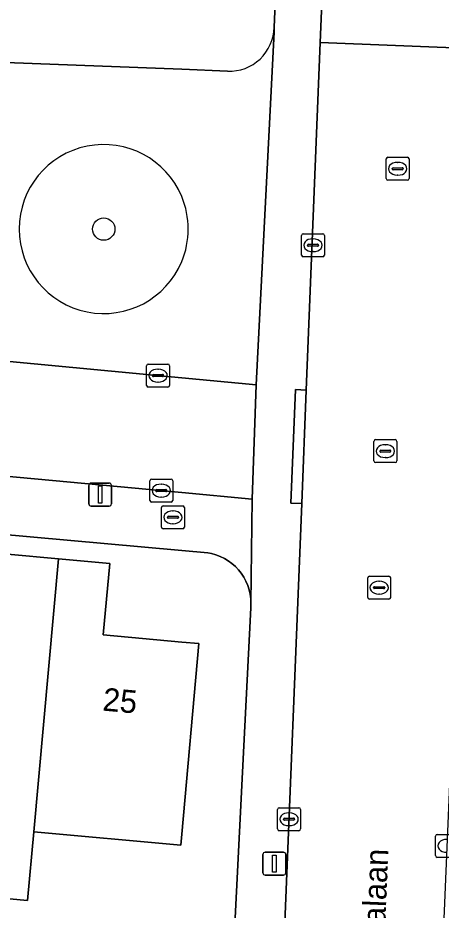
# Model space of a CAD drawing. Extents: x 161354 to 162026, y 386504 to 387460.
# Drawn here: x 161492.87 to 161511.3, y 386914.9 to 386953.74 of the extents above; entities that cross this region are included whole.
import ezdxf

# ---------------------------------------------------------------- set-up
doc = ezdxf.new("R2010")
doc.units = 0
for name, color, linetype in [('IMGEO_Boom', 7, 'Continuous'), ('IMGEO_Brandkraan', 7, 'Continuous'), ('IMGEO_Erf', 7, 'Continuous'), ('IMGEO_Kolk', 7, 'Continuous'), ('IMGEO_Lichtmast', 7, 'Continuous'), ('IMGEO_Muur', 7, 'Continuous'), ('IMGEO_Openbare_ruimte_label', 7, 'Continuous'), ('IMGEO_Pand', 7, 'Continuous'), ('IMGEO_Pand_nummerreeks', 7, 'Continuous'), ('IMGEO_Rijbaan_lokaal_open', 7, 'Continuous'), ('IMGEO_Rioolput', 7, 'Continuous'), ('IMGEO_Terreindeel_open', 7, 'Continuous'), ('IMGEO_Voetpad_open', 7, 'Continuous')]:
    doc.layers.add(name, color=color, linetype=linetype)

msp = doc.modelspace()

# ---------------------------------------------------------------- linework, layer by layer
at = {"layer": 'IMGEO_Boom'}
msp.add_circle((161496.605, 386944.55), 0.489, dxfattribs=at)
at = {"layer": 'IMGEO_Brandkraan'}
for p, q in [((161499.194, 386932.499), (161500.046, 386932.499)), ((161499.119, 386931.573), (161499.119, 386932.425)), ((161499.607, 386932.279), (161499.632, 386932.279)), ((161500.12, 386932.425), (161500.12, 386931.573)), ((161499.378, 386931.993), (161499.378, 386932.005)), ((161499.816, 386931.956), (161499.418, 386931.956)), ((161499.421, 386932.042), (161499.819, 386932.042)), ((161499.63, 386931.719), (161499.605, 386931.719)), ((161499.862, 386932.005), (161499.862, 386931.993)), ((161500.046, 386931.499), (161499.194, 386931.499))]:
    msp.add_line(p, q, dxfattribs=at)
for points in [[(161499.194, 386932.499), (161500.046, 386932.499)], [(161499.119, 386931.573), (161499.119, 386932.425)], [(161500.12, 386932.425), (161500.12, 386931.573)], [(161500.046, 386931.499), (161499.194, 386931.499)]]:
    msp.add_lwpolyline(points, dxfattribs=at)
for centre, radius, start, end in [((161499.196, 386932.423), 0.0765, 91.552, 178.448), ((161499.196, 386932.423), 0.0765, 91.552, 178.448), ((161500.044, 386932.423), 0.0765, 1.552, 88.448), ((161500.044, 386932.423), 0.0765, 1.552, 88.448), ((161499.418, 386932.002), 0.0403, 85.8775, 175.7526), ((161499.415, 386931.992), 0.0366, 178.938, 274.7102), ((161499.819, 386931.999), 0.043, 264.8664, 352.4533), ((161499.823, 386932.004), 0.0386, 1.7309, 96.639), ((161499.196, 386931.575), 0.0765, 181.552, 268.448), ((161499.196, 386931.575), 0.0765, 181.552, 268.448), ((161500.044, 386931.575), 0.0765, 271.552, 358.448), ((161500.044, 386931.575), 0.0765, 271.552, 358.448)]:
    msp.add_arc(centre, radius, start, end, dxfattribs=at)
for centre, major_axis, ratio, start_param, end_param in [((161499.606, 386931.999), (-0.387, 0.002), 0.722429, 4.712389, 7.853982), ((161499.631, 386931.999), (-0.39, 0.002), 0.717154, 1.570796, 4.712389)]:
    msp.add_ellipse(centre, major_axis=major_axis, ratio=ratio, start_param=start_param, end_param=end_param, dxfattribs=at)
at = {"layer": 'IMGEO_Erf'}
for points in [[(161504.021, 386953.33), (161504.232, 386958.325)], [(161429.855, 386954.16), (161500, 386951.511), (161502.002, 386951.426)], [(161502.252, 386913.113), (161502.647, 386920.904), (161503.008, 386928.059), (161503.017, 386928.258), (161503.009, 386928.456), (161502.982, 386928.653), (161502.938, 386928.847), (161502.878, 386929.036), (161502.8, 386929.219), (161502.706, 386929.395), (161502.597, 386929.561), (161502.474, 386929.717), (161502.337, 386929.861), (161502.188, 386929.992), (161502.028, 386930.11), (161501.858, 386930.213), (161501.679, 386930.3), (161501.493, 386930.371), (161501.302, 386930.425), (161501.138, 386930.457), (161500, 386930.56), (161439.113, 386936.044)], [(161492.422, 386930.389), (161494.642, 386930.187), (161496.866, 386929.985), (161496.584, 386926.877), (161500, 386926.567), (161500.753, 386926.499), (161500, 386918.206), (161499.956, 386917.721), (161493.563, 386918.301), (161493.292, 386915.317), (161487.143, 386915.876)]]:
    msp.add_lwpolyline(points, dxfattribs=at)
msp.add_arc((161502.081, 386953.365), 1.941, 267.6727, 358.9691, dxfattribs=at)
at = {"layer": 'IMGEO_Kolk'}
for p, q in [((161505.217, 386943.419), (161505.217, 386944.271)), ((161505.292, 386944.345), (161506.144, 386944.345)), ((161505.705, 386944.125), (161505.73, 386944.125)), ((161506.218, 386944.271), (161506.218, 386943.419)), ((161505.476, 386943.839), (161505.476, 386943.851)), ((161505.914, 386943.802), (161505.516, 386943.802)), ((161505.519, 386943.888), (161505.917, 386943.888)), ((161505.96, 386943.851), (161505.96, 386943.839)), ((161506.144, 386943.345), (161505.292, 386943.345)), ((161505.728, 386943.565), (161505.703, 386943.565)), ((161498.547, 386938.67), (161499.399, 386938.67)), ((161498.472, 386937.744), (161498.472, 386938.596)), ((161498.96, 386938.45), (161498.985, 386938.45)), ((161499.473, 386938.596), (161499.473, 386937.744)), ((161498.731, 386938.164), (161498.731, 386938.176)), ((161499.169, 386938.127), (161498.771, 386938.127)), ((161498.774, 386938.213), (161499.172, 386938.213)), ((161498.983, 386937.89), (161498.958, 386937.89)), ((161499.215, 386938.176), (161499.215, 386938.164)), ((161499.399, 386937.67), (161498.547, 386937.67)), ((161498.688, 386933.663), (161499.54, 386933.663)), ((161498.613, 386932.737), (161498.613, 386933.589)), ((161499.101, 386933.443), (161499.126, 386933.443)), ((161499.614, 386933.589), (161499.614, 386932.737)), ((161498.872, 386933.157), (161498.872, 386933.169)), ((161499.31, 386933.12), (161498.912, 386933.12)), ((161498.915, 386933.206), (161499.313, 386933.206)), ((161499.124, 386932.883), (161499.099, 386932.883)), ((161499.356, 386933.169), (161499.356, 386933.157)), ((161499.54, 386932.663), (161498.688, 386932.663)), ((161504.176, 386918.429), (161504.176, 386919.281)), ((161504.251, 386919.355), (161505.103, 386919.355)), ((161505.177, 386919.281), (161505.177, 386918.429)), ((161504.435, 386918.849), (161504.435, 386918.861)), ((161504.478, 386918.898), (161504.876, 386918.898)), ((161504.664, 386919.135), (161504.689, 386919.135)), ((161504.919, 386918.861), (161504.919, 386918.849)), ((161504.873, 386918.812), (161504.475, 386918.812)), ((161504.687, 386918.575), (161504.662, 386918.575)), ((161505.103, 386918.355), (161504.251, 386918.355)), ((161511.056, 386917.269), (161511.056, 386918.121)), ((161511.131, 386918.195), (161511.983, 386918.195)), ((161511.983, 386917.195), (161511.131, 386917.195))]:
    msp.add_line(p, q, dxfattribs=at)
for points in [[(161505.217, 386943.419), (161505.217, 386944.271)], [(161505.292, 386944.345), (161506.144, 386944.345)], [(161506.218, 386944.271), (161506.218, 386943.419)], [(161506.144, 386943.345), (161505.292, 386943.345)], [(161498.547, 386938.67), (161499.399, 386938.67)], [(161498.472, 386937.744), (161498.472, 386938.596)], [(161499.473, 386938.596), (161499.473, 386937.744)], [(161499.399, 386937.67), (161498.547, 386937.67)], [(161498.688, 386933.663), (161499.54, 386933.663)], [(161498.613, 386932.737), (161498.613, 386933.589)], [(161499.614, 386933.589), (161499.614, 386932.737)], [(161499.54, 386932.663), (161498.688, 386932.663)], [(161504.176, 386918.429), (161504.176, 386919.281)], [(161504.251, 386919.355), (161505.103, 386919.355)], [(161505.177, 386919.281), (161505.177, 386918.429)], [(161505.103, 386918.355), (161504.251, 386918.355)], [(161511.056, 386917.269), (161511.056, 386918.121)], [(161511.131, 386918.195), (161511.983, 386918.195)], [(161511.983, 386917.195), (161511.131, 386917.195)]]:
    msp.add_lwpolyline(points, dxfattribs=at)
for centre, radius, start, end in [((161505.294, 386944.269), 0.0765, 91.552, 178.448), ((161505.294, 386944.269), 0.0765, 91.552, 178.448), ((161506.142, 386944.269), 0.0765, 1.552, 88.448), ((161506.142, 386944.269), 0.0765, 1.552, 88.448), ((161505.516, 386943.848), 0.0403, 85.8775, 175.7526), ((161505.513, 386943.838), 0.0366, 178.938, 274.7102), ((161505.917, 386943.845), 0.043, 264.8664, 352.4533), ((161505.921, 386943.85), 0.0386, 1.7309, 96.639), ((161505.294, 386943.421), 0.0765, 181.552, 268.448), ((161505.294, 386943.421), 0.0765, 181.552, 268.448), ((161506.142, 386943.421), 0.0765, 271.552, 358.448), ((161506.142, 386943.421), 0.0765, 271.552, 358.448), ((161498.549, 386938.594), 0.0765, 91.552, 178.448), ((161498.549, 386938.594), 0.0765, 91.552, 178.448), ((161499.397, 386938.594), 0.0765, 1.552, 88.448), ((161499.397, 386938.594), 0.0765, 1.552, 88.448), ((161498.771, 386938.173), 0.0403, 85.8775, 175.7526), ((161498.768, 386938.163), 0.0366, 178.938, 274.7102), ((161499.172, 386938.17), 0.043, 264.8664, 352.4533), ((161499.176, 386938.175), 0.0386, 1.7309, 96.639), ((161498.549, 386937.746), 0.0765, 181.552, 268.448), ((161498.549, 386937.746), 0.0765, 181.552, 268.448), ((161499.397, 386937.746), 0.0765, 271.552, 358.448), ((161499.397, 386937.746), 0.0765, 271.552, 358.448), ((161498.69, 386933.587), 0.0765, 91.552, 178.448), ((161498.69, 386933.587), 0.0765, 91.552, 178.448), ((161499.538, 386933.587), 0.0765, 1.552, 88.448), ((161499.538, 386933.587), 0.0765, 1.552, 88.448), ((161498.912, 386933.166), 0.0403, 85.8775, 175.7526), ((161498.909, 386933.156), 0.0366, 178.938, 274.7102), ((161499.313, 386933.163), 0.043, 264.8664, 352.4533), ((161499.317, 386933.168), 0.0386, 1.7309, 96.639), ((161498.69, 386932.739), 0.0765, 181.552, 268.448), ((161498.69, 386932.739), 0.0765, 181.552, 268.448), ((161499.538, 386932.739), 0.0765, 271.552, 358.448), ((161499.538, 386932.739), 0.0765, 271.552, 358.448), ((161504.253, 386919.279), 0.0765, 91.552, 178.448), ((161504.253, 386919.279), 0.0765, 91.552, 178.448), ((161505.101, 386919.279), 0.0765, 1.552, 88.448), ((161505.101, 386919.279), 0.0765, 1.552, 88.448), ((161504.475, 386918.858), 0.0403, 85.8775, 175.7526), ((161504.88, 386918.86), 0.0386, 1.7309, 96.639), ((161504.472, 386918.848), 0.0366, 178.938, 274.7102), ((161504.876, 386918.855), 0.043, 264.8664, 352.4533), ((161504.253, 386918.431), 0.0765, 181.552, 268.448), ((161504.253, 386918.431), 0.0765, 181.552, 268.448), ((161505.101, 386918.431), 0.0765, 271.552, 358.448), ((161505.101, 386918.431), 0.0765, 271.552, 358.448), ((161511.133, 386918.119), 0.0765, 91.552, 178.448), ((161511.133, 386918.119), 0.0765, 91.552, 178.448), ((161511.133, 386917.271), 0.0765, 181.552, 268.448), ((161511.133, 386917.271), 0.0765, 181.552, 268.448)]:
    msp.add_arc(centre, radius, start, end, dxfattribs=at)
for centre, major_axis, ratio, start_param, end_param in [((161505.704, 386943.845), (-0.387, 0.002), 0.722429, 4.712389, 7.853982), ((161505.729, 386943.845), (-0.39, 0.002), 0.717154, 1.570796, 4.712389), ((161498.959, 386938.17), (-0.387, 0.002), 0.722429, 4.712389, 7.853982), ((161498.984, 386938.17), (-0.39, 0.002), 0.717154, 1.570796, 4.712389), ((161499.1, 386933.163), (-0.387, 0.002), 0.722429, 4.712389, 7.853982), ((161499.125, 386933.163), (-0.39, 0.002), 0.717154, 1.570796, 4.712389), ((161504.663, 386918.855), (-0.387, 0.002), 0.722429, 4.712389, 7.853982), ((161504.688, 386918.855), (-0.39, 0.002), 0.717154, 1.570796, 4.712389), ((161511.543, 386917.695), (-0.387, 0.002), 0.722429, 4.712389, 7.853982)]:
    msp.add_ellipse(centre, major_axis=major_axis, ratio=ratio, start_param=start_param, end_param=end_param, dxfattribs=at)
at = {"layer": 'IMGEO_Lichtmast'}
for p, q in [((161495.954, 386932.59), (161495.954, 386933.39)), ((161495.954, 386933.39), (161495.954, 386932.59)), ((161496.054, 386933.49), (161496.844, 386933.49)), ((161496.844, 386933.49), (161496.054, 386933.49)), ((161496.944, 386933.39), (161496.944, 386932.59)), ((161496.944, 386932.59), (161496.944, 386933.39)), ((161496.844, 386932.49), (161496.054, 386932.49)), ((161496.054, 386932.49), (161496.844, 386932.49)), ((161503.54, 386916.519), (161503.54, 386917.319)), ((161503.54, 386917.319), (161503.54, 386916.519)), ((161503.64, 386917.419), (161504.43, 386917.419)), ((161504.43, 386917.419), (161503.64, 386917.419)), ((161504.53, 386917.319), (161504.53, 386916.519)), ((161504.53, 386916.519), (161504.53, 386917.319)), ((161504.43, 386916.419), (161503.64, 386916.419)), ((161503.64, 386916.419), (161504.43, 386916.419))]:
    msp.add_line(p, q, dxfattribs=at)
for points in [[(161496.374, 386933.365), (161496.524, 386933.365), (161496.524, 386932.615), (161496.374, 386932.615), (161496.374, 386933.365)], [(161503.96, 386917.294), (161504.11, 386917.294), (161504.11, 386916.544), (161503.96, 386916.544), (161503.96, 386917.294)]]:
    msp.add_lwpolyline(points, dxfattribs=at)
for centre, start, end in [((161496.054, 386933.39), 90, 180), ((161496.054, 386933.39), 90, 180), ((161496.844, 386933.39), 0, 90), ((161496.844, 386933.39), 360, 90), ((161496.054, 386932.59), 180, 270), ((161496.054, 386932.59), 180, 270), ((161496.844, 386932.59), 270, 0), ((161496.844, 386932.59), 270, 0), ((161503.64, 386917.319), 90, 180), ((161503.64, 386917.319), 90, 180), ((161504.43, 386917.319), 0, 90), ((161504.43, 386917.319), 360, 90), ((161503.64, 386916.519), 180, 270), ((161503.64, 386916.519), 180, 270), ((161504.43, 386916.519), 270, 0), ((161504.43, 386916.519), 270, 0)]:
    msp.add_arc(centre, 0.1, start, end, dxfattribs=at)
at = {"layer": 'IMGEO_Muur'}
msp.add_lwpolyline([(161502.647, 386920.904), (161502.252, 386913.113)], dxfattribs=at)
at = {"layer": 'IMGEO_Pand'}
for points in [[(161494.642, 386930.187), (161492.422, 386930.389), (161492.137, 386927.25), (161488.208, 386927.607), (161487.414, 386918.86), (161487.143, 386915.876), (161493.292, 386915.317), (161493.563, 386918.301)], [(161493.563, 386918.301), (161499.956, 386917.721), (161500, 386918.206), (161500.753, 386926.499), (161500, 386926.567), (161496.584, 386926.877), (161496.866, 386929.985), (161494.642, 386930.187)]]:
    msp.add_lwpolyline(points, close=True, dxfattribs=at)
at = {"layer": 'IMGEO_Rijbaan_lokaal_open'}
for points in [[(161513.065, 386955.173), (161506.146, 386955.446), (161506.035, 386952.669), (161512.956, 386952.396)], [(161511.712, 386921.424), (161511.686, 386921.771), (161512.422, 386939.603), (161512.465, 386939.948), (161512.956, 386952.396), (161506.035, 386952.669), (161505.425, 386937.538), (161505.226, 386932.595), (161504.432, 386912.928), (161504.179, 386906.584), (161503.41, 386887.521), (161510.279, 386887.244)]]:
    msp.add_lwpolyline(points, close=True, dxfattribs=at)
for points in [[(161503.242, 386937.762), (161500, 386938.07), (161471.205, 386940.807)], [(161441.171, 386938.543), (161500, 386933.081), (161503.075, 386932.796), (161503.242, 386937.762)]]:
    msp.add_lwpolyline(points, dxfattribs=at)
at = {"layer": 'IMGEO_Rioolput'}
for p, q in [((161508.903, 386946.748), (161508.903, 386947.6)), ((161508.978, 386947.674), (161509.83, 386947.674)), ((161509.904, 386947.6), (161509.904, 386946.748)), ((161509.205, 386947.217), (161509.603, 386947.217)), ((161509.391, 386947.454), (161509.416, 386947.454)), ((161509.162, 386947.168), (161509.162, 386947.18)), ((161509.6, 386947.131), (161509.202, 386947.131)), ((161509.414, 386946.894), (161509.389, 386946.894)), ((161509.646, 386947.18), (161509.646, 386947.168)), ((161509.83, 386946.674), (161508.978, 386946.674)), ((161508.367, 386934.454), (161508.367, 386935.306)), ((161508.442, 386935.38), (161509.294, 386935.38)), ((161509.368, 386935.306), (161509.368, 386934.454)), ((161508.626, 386934.874), (161508.626, 386934.886)), ((161509.064, 386934.837), (161508.666, 386934.837)), ((161508.669, 386934.923), (161509.067, 386934.923)), ((161508.855, 386935.16), (161508.88, 386935.16)), ((161509.11, 386934.886), (161509.11, 386934.874)), ((161508.878, 386934.6), (161508.853, 386934.6)), ((161509.294, 386934.38), (161508.442, 386934.38)), ((161508.098, 386928.51), (161508.098, 386929.362)), ((161508.173, 386929.436), (161509.025, 386929.436)), ((161509.099, 386929.362), (161509.099, 386928.51)), ((161508.4, 386928.979), (161508.798, 386928.979)), ((161508.586, 386929.216), (161508.611, 386929.216)), ((161508.357, 386928.93), (161508.357, 386928.942)), ((161508.795, 386928.893), (161508.397, 386928.893)), ((161508.609, 386928.656), (161508.584, 386928.656)), ((161508.841, 386928.942), (161508.841, 386928.93)), ((161509.025, 386928.436), (161508.173, 386928.436))]:
    msp.add_line(p, q, dxfattribs=at)
for points in [[(161508.903, 386946.748), (161508.903, 386947.6)], [(161508.978, 386947.674), (161509.83, 386947.674)], [(161509.904, 386947.6), (161509.904, 386946.748)], [(161509.83, 386946.674), (161508.978, 386946.674)], [(161508.367, 386934.454), (161508.367, 386935.306)], [(161508.442, 386935.38), (161509.294, 386935.38)], [(161509.368, 386935.306), (161509.368, 386934.454)], [(161509.294, 386934.38), (161508.442, 386934.38)], [(161508.098, 386928.51), (161508.098, 386929.362)], [(161508.173, 386929.436), (161509.025, 386929.436)], [(161509.099, 386929.362), (161509.099, 386928.51)], [(161509.025, 386928.436), (161508.173, 386928.436)]]:
    msp.add_lwpolyline(points, dxfattribs=at)
for centre, radius, start, end in [((161508.98, 386947.598), 0.0765, 91.552, 178.448), ((161508.98, 386947.598), 0.0765, 91.552, 178.448), ((161509.828, 386947.598), 0.0765, 1.552, 88.448), ((161509.828, 386947.598), 0.0765, 1.552, 88.448), ((161509.202, 386947.177), 0.0403, 85.8775, 175.7526), ((161509.607, 386947.179), 0.0386, 1.7309, 96.639), ((161509.199, 386947.167), 0.0366, 178.938, 274.7102), ((161509.603, 386947.174), 0.043, 264.8664, 352.4533), ((161508.98, 386946.75), 0.0765, 181.552, 268.448), ((161508.98, 386946.75), 0.0765, 181.552, 268.448), ((161509.828, 386946.75), 0.0765, 271.552, 358.448), ((161509.828, 386946.75), 0.0765, 271.552, 358.448), ((161508.444, 386935.304), 0.0765, 91.552, 178.448), ((161508.444, 386935.304), 0.0765, 91.552, 178.448), ((161509.292, 386935.304), 0.0765, 1.552, 88.448), ((161509.292, 386935.304), 0.0765, 1.552, 88.448), ((161508.666, 386934.883), 0.0403, 85.8775, 175.7526), ((161508.663, 386934.873), 0.0366, 178.938, 274.7102), ((161509.067, 386934.88), 0.043, 264.8664, 352.4533), ((161509.071, 386934.885), 0.0386, 1.7309, 96.639), ((161508.444, 386934.456), 0.0765, 181.552, 268.448), ((161508.444, 386934.456), 0.0765, 181.552, 268.448), ((161509.292, 386934.456), 0.0765, 271.552, 358.448), ((161509.292, 386934.456), 0.0765, 271.552, 358.448), ((161508.175, 386929.36), 0.0765, 91.552, 178.448), ((161508.175, 386929.36), 0.0765, 91.552, 178.448), ((161509.023, 386929.36), 0.0765, 1.552, 88.448), ((161509.023, 386929.36), 0.0765, 1.552, 88.448), ((161508.397, 386928.939), 0.0403, 85.8775, 175.7526), ((161508.802, 386928.941), 0.0386, 1.7309, 96.639), ((161508.394, 386928.929), 0.0366, 178.938, 274.7102), ((161508.798, 386928.936), 0.043, 264.8664, 352.4533), ((161508.175, 386928.512), 0.0765, 181.552, 268.448), ((161508.175, 386928.512), 0.0765, 181.552, 268.448), ((161509.023, 386928.512), 0.0765, 271.552, 358.448), ((161509.023, 386928.512), 0.0765, 271.552, 358.448)]:
    msp.add_arc(centre, radius, start, end, dxfattribs=at)
for centre, major_axis, ratio, start_param, end_param in [((161509.39, 386947.174), (-0.387, 0.002), 0.722429, 4.712389, 7.853982), ((161509.415, 386947.174), (-0.39, 0.002), 0.717154, 1.570796, 4.712389), ((161508.854, 386934.88), (-0.387, 0.002), 0.722429, 4.712389, 7.853982), ((161508.879, 386934.88), (-0.39, 0.002), 0.717154, 1.570796, 4.712389), ((161508.585, 386928.936), (-0.387, 0.002), 0.722429, 4.712389, 7.853982), ((161508.61, 386928.936), (-0.39, 0.002), 0.717154, 1.570796, 4.712389)]:
    msp.add_ellipse(centre, major_axis=major_axis, ratio=ratio, start_param=start_param, end_param=end_param, dxfattribs=at)
at = {"layer": 'IMGEO_Terreindeel_open'}
for start, end in [(22.6977, 337.3023), (337.3026, 22.6974)]:
    msp.add_arc((161496.605, 386944.55), 3.68, start, end, dxfattribs=at)
at = {"layer": 'IMGEO_Voetpad_open'}
for points in [[(161504.232, 386958.325), (161504.021, 386953.33), (161504.031, 386953.115), (161503.242, 386937.762), (161503.075, 386932.796), (161503.017, 386928.258), (161503.008, 386928.059), (161502.647, 386920.904), (161502.252, 386913.113), (161502.142, 386909.931), (161502.031, 386906.749), (161501.966, 386905.208), (161501.498, 386894.157), (161501.172, 386886.081), (161501.061, 386880.675)], [(161502.894, 386875.753), (161503.297, 386884.723), (161503.41, 386887.521), (161504.179, 386906.584), (161503.668, 386906.604), (161503.933, 386912.948), (161504.432, 386912.928), (161505.226, 386932.595), (161504.752, 386932.616), (161504.957, 386937.559), (161505.425, 386937.538), (161506.035, 386952.669), (161506.146, 386955.446)], [(161502.002, 386951.426), (161500, 386951.511), (161429.855, 386954.16), (161428.171, 386954.217), (161404.423, 386955.184)], [(161471.205, 386940.807), (161500, 386938.07), (161503.242, 386937.762), (161504.031, 386953.115), (161504.021, 386953.33)], [(161439.113, 386936.044), (161500, 386930.56), (161501.138, 386930.457), (161501.302, 386930.425), (161501.493, 386930.371), (161501.679, 386930.3), (161501.858, 386930.213), (161502.028, 386930.11), (161502.188, 386929.992), (161502.337, 386929.861), (161502.474, 386929.717), (161502.597, 386929.561), (161502.706, 386929.395), (161502.8, 386929.219), (161502.878, 386929.036), (161502.938, 386928.847), (161502.982, 386928.653), (161503.009, 386928.456), (161503.017, 386928.258), (161503.075, 386932.796), (161500, 386933.081), (161441.171, 386938.543)]]:
    msp.add_lwpolyline(points, dxfattribs=at)
msp.add_lwpolyline([(161505.226, 386932.595), (161505.425, 386937.538), (161504.957, 386937.559), (161504.752, 386932.616)], close=True, dxfattribs=at)
for centre, radius, start, end in [((161502.081, 386953.365), 1.941, 267.6727, 358.9691), ((161496.605, 386944.55), 3.68, 22.6977, 337.3023), ((161496.605, 386944.55), 3.68, 337.3026, 22.6974)]:
    msp.add_arc(centre, radius, start, end, dxfattribs=at)

# ---------------------------------------------------------------- texts
at = {"layer": 'IMGEO_Openbare_ruimte_label'}
msp.add_text('Samarialaan', height=1, rotation=87.6498, dxfattribs=at).set_placement((161508.692, 386910.047))
at = {"layer": 'IMGEO_Pand_nummerreeks'}
msp.add_text('25', height=1, rotation=354.8329, dxfattribs=at).set_placement((161496.531, 386923.587))

doc.saveas('drawing.dxf')
